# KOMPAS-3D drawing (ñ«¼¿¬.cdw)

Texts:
  кеменова
  Текст на чертеже
  Размерные надписи
  Шероховатость
  Линия-выноска #1
  Линия-выноска #2
  Линия-выноска #3
  Отклонения формы и база
  Заголовок таблицы
  Ячейка таблицы
  Стрелка вида
  Обозначение изменения
  Фигурная скобка
  Номер узла
  Марка координационной оси
  VRCB
  Выносная надпись
  Обозначение узла
  Марка/позиционное обозначение с линией-выноской
  Марка/позиционное обозначение на линии
  Марка/позиционное обозначение без линии-выноски
Dimensions and other numbers on the sheet: 7; 110; 1:1; 1; 0; 2; 3; 4; 5; 6; 8; 9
